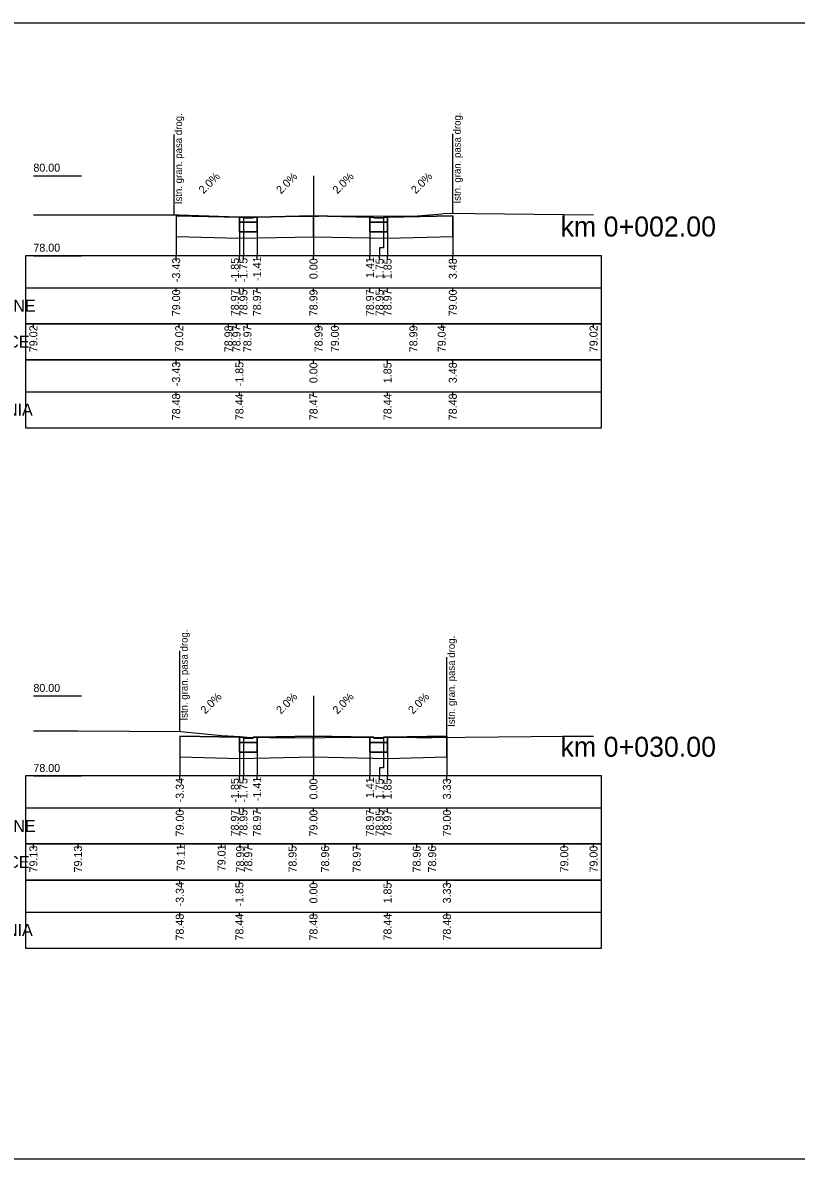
# Model space of a CAD drawing. Extents: x 7492871 to 7493499, y 5802964 to 5802992.
# Drawn here: x 7493176.28 to 7493195.61, y 5802963.88 to 5802992.28 of the extents above; entities that cross this region are included whole.
import ezdxf

# ---------------------------------------------------------------- set-up
doc = ezdxf.new("R2010")
doc.units = 0
for name, color, linetype in [('_wydruk', 7, 'Continuous'), ('opisy_ramki_pop', 7, 'Continuous'), ('pop_comp_kostka', 7, 'Continuous'), ('pop_comp_lawa', 7, 'Continuous'), ('pop_comp_scieralna', 7, 'Continuous'), ('pop_granica_istn', 7, 'Continuous'), ('pop_opis', 7, 'Continuous'), ('pop_os', 7, 'Continuous'), ('pop_pikietaz', 7, 'Continuous'), ('pop_teren', 7, 'Continuous')]:
    doc.layers.add(name, color=color, linetype=linetype)

msp = doc.modelspace()

# ---------------------------------------------------------------- linework, layer by layer
for points in [[(7493180.111, 5802987.456), (7493181.692, 5802987.425), (7493181.792, 5802987.425), (7493181.793, 5802987.405), (7493182.032, 5802987.405), (7493182.033, 5802987.425), (7493182.133, 5802987.425), (7493183.543, 5802987.453), (7493184.953, 5802987.425), (7493185.053, 5802987.425), (7493185.054, 5802987.405), (7493185.293, 5802987.405), (7493185.294, 5802987.425), (7493185.394, 5802987.425), (7493187.025, 5802987.457)], [(7493180.201, 5802974.456), (7493181.692, 5802974.426), (7493181.792, 5802974.426), (7493181.793, 5802974.406), (7493182.032, 5802974.406), (7493182.033, 5802974.426), (7493182.133, 5802974.426), (7493183.543, 5802974.454), (7493184.953, 5802974.426), (7493185.053, 5802974.426), (7493185.054, 5802974.406), (7493185.293, 5802974.406), (7493185.294, 5802974.426), (7493185.394, 5802974.426), (7493186.877, 5802974.456)]]:
    msp.add_lwpolyline(points)
at = {"layer": '_wydruk'}
msp.add_lwpolyline([(7492871.369, 5802992.281), (7493499.283, 5802992.281), (7493499.283, 5802963.881), (7492871.369, 5802963.881)], close=True, dxfattribs=at)
at = {"layer": 'opisy_ramki_pop'}
for points in [[(7493180.111, 5802986.936), (7493180.111, 5802986.659), (7493180.111, 5802986.659), (7493180.111, 5802986.459)], [(7493181.692, 5802986.896), (7493181.692, 5802986.659), (7493181.692, 5802986.659), (7493181.692, 5802986.459)], [(7493183.543, 5802986.933), (7493183.543, 5802986.659), (7493183.543, 5802986.659), (7493183.543, 5802986.459)], [(7493185.394, 5802986.896), (7493185.394, 5802986.659), (7493185.394, 5802986.659), (7493185.394, 5802986.459)], [(7493187.025, 5802986.937), (7493187.025, 5802986.659), (7493187.025, 5802986.659), (7493187.025, 5802986.459)], [(7493180.201, 5802973.936), (7493180.201, 5802973.659), (7493180.201, 5802973.659), (7493180.201, 5802973.459)], [(7493181.692, 5802973.897), (7493181.692, 5802973.659), (7493181.692, 5802973.659), (7493181.692, 5802973.459)], [(7493183.543, 5802973.934), (7493183.543, 5802973.659), (7493183.543, 5802973.659), (7493183.543, 5802973.459)], [(7493185.394, 5802973.897), (7493185.394, 5802973.659), (7493185.394, 5802973.659), (7493185.394, 5802973.459)], [(7493186.877, 5802973.936), (7493186.877, 5802973.659), (7493186.877, 5802973.659), (7493186.877, 5802973.459)]]:
    msp.add_lwpolyline(points, dxfattribs=at)
at = {"layer": 'pop_comp_kostka'}
for p, q in [((7493181.792, 5802987.425), (7493181.692, 5802987.425)), ((7493181.692, 5802987.425), (7493181.692, 5802987.295)), ((7493181.793, 5802987.405), (7493181.792, 5802987.425)), ((7493182.032, 5802987.405), (7493181.793, 5802987.405)), ((7493182.033, 5802987.425), (7493182.032, 5802987.405)), ((7493182.133, 5802987.425), (7493182.033, 5802987.425)), ((7493182.133, 5802987.295), (7493182.133, 5802987.425)), ((7493185.053, 5802987.425), (7493184.953, 5802987.425)), ((7493184.953, 5802987.425), (7493184.953, 5802987.295)), ((7493185.054, 5802987.405), (7493185.053, 5802987.425)), ((7493185.293, 5802987.405), (7493185.054, 5802987.405)), ((7493185.294, 5802987.425), (7493185.293, 5802987.405)), ((7493185.394, 5802987.425), (7493185.294, 5802987.425)), ((7493185.394, 5802987.295), (7493185.394, 5802987.425)), ((7493181.692, 5802987.295), (7493182.133, 5802987.295)), ((7493184.953, 5802987.295), (7493185.394, 5802987.295)), ((7493181.792, 5802974.426), (7493181.692, 5802974.426)), ((7493181.692, 5802974.426), (7493181.692, 5802974.296)), ((7493181.692, 5802974.296), (7493182.133, 5802974.296)), ((7493181.793, 5802974.406), (7493181.792, 5802974.426)), ((7493182.032, 5802974.406), (7493181.793, 5802974.406)), ((7493182.033, 5802974.426), (7493182.032, 5802974.406)), ((7493182.133, 5802974.426), (7493182.033, 5802974.426)), ((7493182.133, 5802974.296), (7493182.133, 5802974.426)), ((7493185.053, 5802974.426), (7493184.953, 5802974.426)), ((7493184.953, 5802974.426), (7493184.953, 5802974.296)), ((7493184.953, 5802974.296), (7493185.394, 5802974.296)), ((7493185.054, 5802974.406), (7493185.053, 5802974.426)), ((7493185.293, 5802974.406), (7493185.054, 5802974.406)), ((7493185.294, 5802974.426), (7493185.293, 5802974.406)), ((7493185.394, 5802974.426), (7493185.294, 5802974.426)), ((7493185.394, 5802974.296), (7493185.394, 5802974.426))]:
    msp.add_line(p, q, dxfattribs=at)
at = {"layer": 'pop_comp_lawa'}
for p, q in [((7493182.133, 5802987.295), (7493181.692, 5802987.295)), ((7493181.692, 5802987.295), (7493181.692, 5802987.055)), ((7493181.692, 5802987.055), (7493182.133, 5802987.055)), ((7493182.133, 5802987.055), (7493182.133, 5802987.295)), ((7493185.394, 5802987.295), (7493184.953, 5802987.295)), ((7493184.953, 5802987.295), (7493184.953, 5802987.055)), ((7493184.953, 5802987.055), (7493185.394, 5802987.055)), ((7493185.394, 5802987.055), (7493185.394, 5802987.295)), ((7493182.133, 5802974.296), (7493181.692, 5802974.296)), ((7493181.692, 5802974.296), (7493181.692, 5802974.056)), ((7493182.133, 5802974.056), (7493182.133, 5802974.296)), ((7493185.394, 5802974.296), (7493184.953, 5802974.296)), ((7493184.953, 5802974.296), (7493184.953, 5802974.056)), ((7493185.394, 5802974.056), (7493185.394, 5802974.296)), ((7493181.692, 5802974.056), (7493182.133, 5802974.056)), ((7493184.953, 5802974.056), (7493185.394, 5802974.056))]:
    msp.add_line(p, q, dxfattribs=at)
at = {"layer": 'pop_comp_scieralna'}
for p, q in [((7493181.692, 5802987.425), (7493180.111, 5802987.456)), ((7493180.111, 5802987.456), (7493180.111, 5802986.936)), ((7493181.692, 5802987.055), (7493181.692, 5802987.425)), ((7493183.543, 5802987.453), (7493182.133, 5802987.425)), ((7493182.133, 5802987.425), (7493182.133, 5802987.055)), ((7493183.543, 5802986.933), (7493183.543, 5802987.453)), ((7493184.953, 5802987.425), (7493183.543, 5802987.453)), ((7493183.543, 5802987.453), (7493183.543, 5802986.933)), ((7493184.953, 5802987.055), (7493184.953, 5802987.425)), ((7493187.025, 5802987.457), (7493185.394, 5802987.425)), ((7493185.394, 5802987.425), (7493185.394, 5802987.055)), ((7493187.025, 5802986.937), (7493187.025, 5802987.457)), ((7493182.133, 5802987.055), (7493181.692, 5802987.055)), ((7493185.394, 5802987.055), (7493184.953, 5802987.055)), ((7493180.111, 5802986.936), (7493181.692, 5802986.896)), ((7493181.692, 5802986.896), (7493183.543, 5802986.933)), ((7493183.543, 5802986.933), (7493185.394, 5802986.896)), ((7493185.394, 5802986.896), (7493187.025, 5802986.937)), ((7493181.692, 5802974.426), (7493180.201, 5802974.456)), ((7493180.201, 5802974.456), (7493180.201, 5802973.936)), ((7493181.692, 5802974.056), (7493181.692, 5802974.426)), ((7493183.543, 5802974.454), (7493182.133, 5802974.426)), ((7493182.133, 5802974.426), (7493182.133, 5802974.056)), ((7493183.543, 5802973.934), (7493183.543, 5802974.454)), ((7493184.953, 5802974.426), (7493183.543, 5802974.454)), ((7493183.543, 5802974.454), (7493183.543, 5802973.934)), ((7493184.953, 5802974.056), (7493184.953, 5802974.426)), ((7493186.877, 5802974.456), (7493185.394, 5802974.426)), ((7493185.394, 5802974.426), (7493185.394, 5802974.056)), ((7493186.877, 5802973.936), (7493186.877, 5802974.456)), ((7493182.133, 5802974.056), (7493181.692, 5802974.056)), ((7493185.394, 5802974.056), (7493184.953, 5802974.056)), ((7493180.201, 5802973.936), (7493181.692, 5802973.897)), ((7493181.692, 5802973.897), (7493183.543, 5802973.934)), ((7493183.543, 5802973.934), (7493185.394, 5802973.897)), ((7493185.394, 5802973.897), (7493186.877, 5802973.936))]:
    msp.add_line(p, q, dxfattribs=at)
at = {"layer": 'pop_granica_istn'}
for p, q in [((7493180.06, 5802987.984), (7493180.06, 5802989.484)), ((7493187.025, 5802988.002), (7493187.025, 5802989.502)), ((7493180.06, 5802987.484), (7493180.06, 5802987.984)), ((7493187.025, 5802987.502), (7493187.025, 5802988.002)), ((7493180.201, 5802975.082), (7493180.201, 5802976.582)), ((7493186.88, 5802974.924), (7493186.88, 5802976.424)), ((7493180.201, 5802974.582), (7493180.201, 5802975.082)), ((7493186.88, 5802974.424), (7493186.88, 5802974.924))]:
    msp.add_line(p, q, dxfattribs=at)
at = {"layer": 'pop_opis'}
for p, q in [((7493176.543, 5802988.459), (7493177.743, 5802988.459)), ((7493176.343, 5802986.459), (7493176.343, 5802984.759)), ((7493176.343, 5802986.459), (7493176.343, 5802984.759)), ((7493176.343, 5802986.459), (7493176.343, 5802984.759)), ((7493176.343, 5802986.459), (7493176.343, 5802984.759)), ((7493176.543, 5802986.459), (7493177.743, 5802986.459)), ((7493180.111, 5802986.359), (7493180.111, 5802986.459)), ((7493181.692, 5802986.359), (7493181.692, 5802986.459)), ((7493181.793, 5802986.359), (7493181.793, 5802986.459)), ((7493182.133, 5802986.359), (7493182.133, 5802986.459)), ((7493183.543, 5802986.359), (7493183.543, 5802986.459)), ((7493184.953, 5802986.359), (7493184.953, 5802986.459)), ((7493185.194, 5802986.359), (7493185.194, 5802986.459)), ((7493185.394, 5802986.359), (7493185.394, 5802986.459)), ((7493187.025, 5802986.359), (7493187.025, 5802986.459)), ((7493176.343, 5802985.659), (7493190.743, 5802985.659)), ((7493176.343, 5802985.659), (7493190.743, 5802985.659)), ((7493176.343, 5802985.659), (7493190.743, 5802985.659)), ((7493176.343, 5802985.659), (7493190.743, 5802985.659)), ((7493180.111, 5802985.559), (7493180.111, 5802985.659)), ((7493181.692, 5802985.559), (7493181.692, 5802985.659)), ((7493181.793, 5802985.559), (7493181.793, 5802985.659)), ((7493182.133, 5802985.559), (7493182.133, 5802985.659)), ((7493183.543, 5802985.559), (7493183.543, 5802985.659)), ((7493184.953, 5802985.559), (7493184.953, 5802985.659)), ((7493185.194, 5802985.559), (7493185.194, 5802985.659)), ((7493185.394, 5802985.559), (7493185.394, 5802985.659)), ((7493187.025, 5802985.559), (7493187.025, 5802985.659)), ((7493176.343, 5802984.759), (7493176.343, 5802983.859)), ((7493176.543, 5802984.659), (7493176.543, 5802984.759)), ((7493180.187, 5802984.659), (7493180.187, 5802984.759)), ((7493181.419, 5802984.659), (7493181.419, 5802984.759)), ((7493181.619, 5802984.659), (7493181.619, 5802984.759)), ((7493181.893, 5802984.659), (7493181.893, 5802984.759)), ((7493183.67, 5802984.659), (7493183.67, 5802984.759)), ((7493184.078, 5802984.659), (7493184.078, 5802984.759)), ((7493186.041, 5802984.659), (7493186.041, 5802984.759)), ((7493186.748, 5802984.659), (7493186.748, 5802984.759)), ((7493190.543, 5802984.659), (7493190.543, 5802984.759)), ((7493176.343, 5802983.859), (7493176.343, 5802982.159)), ((7493180.111, 5802983.759), (7493180.111, 5802983.859)), ((7493181.692, 5802983.759), (7493181.692, 5802983.859)), ((7493183.543, 5802983.759), (7493183.543, 5802983.859)), ((7493185.394, 5802983.759), (7493185.394, 5802983.859)), ((7493187.025, 5802983.759), (7493187.025, 5802983.859)), ((7493176.343, 5802983.059), (7493190.743, 5802983.059)), ((7493180.111, 5802982.959), (7493180.111, 5802983.059)), ((7493181.692, 5802982.959), (7493181.692, 5802983.059)), ((7493183.543, 5802982.959), (7493183.543, 5802983.059)), ((7493185.394, 5802982.959), (7493185.394, 5802983.059)), ((7493187.025, 5802982.959), (7493187.025, 5802983.059)), ((7493176.543, 5802975.459), (7493177.743, 5802975.459)), ((7493176.343, 5802973.459), (7493176.343, 5802971.759)), ((7493176.343, 5802973.459), (7493176.343, 5802971.759)), ((7493176.343, 5802973.459), (7493176.343, 5802971.759)), ((7493176.343, 5802973.459), (7493176.343, 5802971.759)), ((7493176.543, 5802973.459), (7493177.743, 5802973.459)), ((7493180.201, 5802973.359), (7493180.201, 5802973.459)), ((7493181.692, 5802973.359), (7493181.692, 5802973.459)), ((7493181.793, 5802973.359), (7493181.793, 5802973.459)), ((7493182.133, 5802973.359), (7493182.133, 5802973.459)), ((7493183.543, 5802973.359), (7493183.543, 5802973.459)), ((7493184.953, 5802973.359), (7493184.953, 5802973.459)), ((7493185.194, 5802973.359), (7493185.194, 5802973.459)), ((7493185.394, 5802973.359), (7493185.394, 5802973.459)), ((7493186.877, 5802973.359), (7493186.877, 5802973.459)), ((7493176.343, 5802972.659), (7493190.743, 5802972.659)), ((7493176.343, 5802972.659), (7493190.743, 5802972.659)), ((7493176.343, 5802972.659), (7493190.743, 5802972.659)), ((7493176.343, 5802972.659), (7493190.743, 5802972.659)), ((7493180.201, 5802972.559), (7493180.201, 5802972.659)), ((7493181.692, 5802972.559), (7493181.692, 5802972.659)), ((7493181.793, 5802972.559), (7493181.793, 5802972.659)), ((7493182.133, 5802972.559), (7493182.133, 5802972.659)), ((7493183.543, 5802972.559), (7493183.543, 5802972.659)), ((7493184.953, 5802972.559), (7493184.953, 5802972.659)), ((7493185.194, 5802972.559), (7493185.194, 5802972.659)), ((7493185.394, 5802972.559), (7493185.394, 5802972.659)), ((7493186.877, 5802972.559), (7493186.877, 5802972.659)), ((7493176.343, 5802971.759), (7493176.343, 5802970.859)), ((7493176.543, 5802971.659), (7493176.543, 5802971.759)), ((7493177.658, 5802971.659), (7493177.658, 5802971.759)), ((7493180.227, 5802971.659), (7493180.227, 5802971.759)), ((7493181.245, 5802971.659), (7493181.245, 5802971.759)), ((7493181.712, 5802971.659), (7493181.712, 5802971.759)), ((7493181.912, 5802971.659), (7493181.912, 5802971.759)), ((7493183.02, 5802971.659), (7493183.02, 5802971.759)), ((7493183.835, 5802971.659), (7493183.835, 5802971.759)), ((7493184.624, 5802971.659), (7493184.624, 5802971.759)), ((7493186.123, 5802971.659), (7493186.123, 5802971.759)), ((7493186.509, 5802971.659), (7493186.509, 5802971.759)), ((7493189.812, 5802971.659), (7493189.812, 5802971.759)), ((7493190.543, 5802971.659), (7493190.543, 5802971.759)), ((7493176.343, 5802970.859), (7493176.343, 5802969.159)), ((7493180.201, 5802970.759), (7493180.201, 5802970.859)), ((7493181.692, 5802970.759), (7493181.692, 5802970.859)), ((7493183.543, 5802970.759), (7493183.543, 5802970.859)), ((7493185.394, 5802970.759), (7493185.394, 5802970.859)), ((7493186.877, 5802970.759), (7493186.877, 5802970.859)), ((7493176.343, 5802970.059), (7493190.743, 5802970.059)), ((7493180.201, 5802969.959), (7493180.201, 5802970.059)), ((7493181.692, 5802969.959), (7493181.692, 5802970.059)), ((7493183.543, 5802969.959), (7493183.543, 5802970.059)), ((7493185.394, 5802969.959), (7493185.394, 5802970.059)), ((7493186.877, 5802969.959), (7493186.877, 5802970.059))]:
    msp.add_line(p, q, dxfattribs=at)
for points in [[(7493180.111, 5802987.456), (7493180.111, 5802986.659), (7493180.111, 5802986.659), (7493180.111, 5802986.459)], [(7493181.692, 5802987.425), (7493181.692, 5802986.659), (7493181.692, 5802986.659), (7493181.692, 5802986.459)], [(7493181.793, 5802987.405), (7493181.793, 5802986.659), (7493181.793, 5802986.659), (7493181.793, 5802986.459)], [(7493182.133, 5802987.425), (7493182.133, 5802986.659), (7493182.133, 5802986.659), (7493182.133, 5802986.459)], [(7493183.543, 5802987.453), (7493183.543, 5802986.659), (7493183.543, 5802986.659), (7493183.543, 5802986.459)], [(7493184.953, 5802987.425), (7493184.953, 5802986.659), (7493184.953, 5802986.659), (7493184.953, 5802986.459)], [(7493185.293, 5802987.405), (7493185.293, 5802986.659), (7493185.194, 5802986.659), (7493185.194, 5802986.459)], [(7493185.394, 5802987.425), (7493185.394, 5802986.659), (7493185.394, 5802986.659), (7493185.394, 5802986.459)], [(7493187.025, 5802987.457), (7493187.025, 5802986.659), (7493187.025, 5802986.659), (7493187.025, 5802986.459)], [(7493180.201, 5802974.456), (7493180.201, 5802973.659), (7493180.201, 5802973.659), (7493180.201, 5802973.459)], [(7493181.692, 5802974.426), (7493181.692, 5802973.659), (7493181.692, 5802973.659), (7493181.692, 5802973.459)], [(7493181.793, 5802974.406), (7493181.793, 5802973.659), (7493181.793, 5802973.659), (7493181.793, 5802973.459)], [(7493182.133, 5802974.426), (7493182.133, 5802973.659), (7493182.133, 5802973.659), (7493182.133, 5802973.459)], [(7493183.543, 5802974.454), (7493183.543, 5802973.659), (7493183.543, 5802973.659), (7493183.543, 5802973.459)], [(7493184.953, 5802974.426), (7493184.953, 5802973.659), (7493184.953, 5802973.659), (7493184.953, 5802973.459)], [(7493185.293, 5802974.406), (7493185.293, 5802973.659), (7493185.194, 5802973.659), (7493185.194, 5802973.459)], [(7493185.394, 5802974.426), (7493185.394, 5802973.659), (7493185.394, 5802973.659), (7493185.394, 5802973.459)], [(7493186.877, 5802974.456), (7493186.877, 5802973.659), (7493186.877, 5802973.659), (7493186.877, 5802973.459)]]:
    msp.add_lwpolyline(points, dxfattribs=at)
for points in [[(7493176.343, 5802986.459), (7493176.343, 5802984.759), (7493190.743, 5802984.759), (7493190.743, 5802986.459)], [(7493176.343, 5802986.459), (7493176.343, 5802984.759), (7493190.743, 5802984.759), (7493190.743, 5802986.459)], [(7493176.343, 5802986.459), (7493176.343, 5802984.759), (7493190.743, 5802984.759), (7493190.743, 5802986.459)], [(7493176.343, 5802986.459), (7493176.343, 5802984.759), (7493190.743, 5802984.759), (7493190.743, 5802986.459)], [(7493176.343, 5802984.759), (7493176.343, 5802983.859), (7493190.743, 5802983.859), (7493190.743, 5802984.759)], [(7493176.343, 5802983.859), (7493176.343, 5802982.159), (7493190.743, 5802982.159), (7493190.743, 5802983.859)], [(7493176.343, 5802973.459), (7493176.343, 5802971.759), (7493190.743, 5802971.759), (7493190.743, 5802973.459)], [(7493176.343, 5802973.459), (7493176.343, 5802971.759), (7493190.743, 5802971.759), (7493190.743, 5802973.459)], [(7493176.343, 5802973.459), (7493176.343, 5802971.759), (7493190.743, 5802971.759), (7493190.743, 5802973.459)], [(7493176.343, 5802973.459), (7493176.343, 5802971.759), (7493190.743, 5802971.759), (7493190.743, 5802973.459)], [(7493176.343, 5802971.759), (7493176.343, 5802970.859), (7493190.743, 5802970.859), (7493190.743, 5802971.759)], [(7493176.343, 5802970.859), (7493176.343, 5802969.159), (7493190.743, 5802969.159), (7493190.743, 5802970.859)]]:
    msp.add_lwpolyline(points, close=True, dxfattribs=at)
at = {"layer": 'pop_os'}
for p, q in [((7493183.543, 5802988.459), (7493183.543, 5802986.459)), ((7493183.543, 5802975.459), (7493183.543, 5802973.459))]:
    msp.add_line(p, q, dxfattribs=at)
at = {"layer": 'pop_teren'}
for points in [[(7493176.543, 5802987.482), (7493180.187, 5802987.478), (7493181.419, 5802987.441), (7493181.593, 5802987.431), (7493181.893, 5802987.431), (7493183.67, 5802987.45), (7493184.078, 5802987.455), (7493186.041, 5802987.444), (7493186.748, 5802987.502), (7493186.84, 5802987.523), (7493190.543, 5802987.482)], [(7493176.543, 5802974.584), (7493177.658, 5802974.585), (7493180.227, 5802974.569), (7493181.245, 5802974.471), (7493181.712, 5802974.446), (7493181.884, 5802974.431), (7493183.02, 5802974.413), (7493183.835, 5802974.42), (7493184.624, 5802974.429), (7493186.123, 5802974.42), (7493186.509, 5802974.418), (7493189.812, 5802974.456), (7493190.543, 5802974.455)]]:
    msp.add_lwpolyline(points, dxfattribs=at)

# ---------------------------------------------------------------- texts
at = {"layer": 'pop_granica_istn'}
for p in [(7493180.258, 5802987.745), (7493187.223, 5802987.763), (7493180.399, 5802974.843), (7493187.078, 5802974.686)]:
    msp.add_text('Istn. gran. pasa drog.', height=0.18, rotation=90, dxfattribs=at).set_placement(p)
at = {"layer": 'pop_opis'}
for s, height, p in [('80.00', 0.2, (7493176.543, 5802988.559)), ('78.00', 0.2, (7493176.543, 5802986.559)), ('RZĘDNE PROJEKTOWANE', 0.3, (7493171.471, 5802985.059)), ('RZĘDNE PROJEKTOWANE', 0.3, (7493171.471, 5802985.059)), ('RZĘDNE PROJEKTOWANE', 0.3, (7493171.471, 5802985.059)), ('RZĘDNE PROJEKTOWANE', 0.3, (7493171.471, 5802985.059)), ('RZĘDNE ISTNIEJĄCE', 0.3, (7493172.367, 5802984.159)), ('RZĘDNE KORYTOWANIA', 0.3, (7493171.757, 5802982.459)), ('80.00', 0.2, (7493176.543, 5802975.559)), ('78.00', 0.2, (7493176.543, 5802973.559)), ('RZĘDNE PROJEKTOWANE', 0.3, (7493171.471, 5802972.059)), ('RZĘDNE PROJEKTOWANE', 0.3, (7493171.471, 5802972.059)), ('RZĘDNE PROJEKTOWANE', 0.3, (7493171.471, 5802972.059)), ('RZĘDNE PROJEKTOWANE', 0.3, (7493171.471, 5802972.059)), ('RZĘDNE ISTNIEJĄCE', 0.3, (7493172.367, 5802971.159)), ('RZĘDNE KORYTOWANIA', 0.3, (7493171.757, 5802969.459))]:
    msp.add_text(s, height=height, dxfattribs=at).set_placement(p)
for s, rotation, p in [('2.0%', 45, (7493180.793, 5802987.99)), ('2.0%', 45, (7493182.729, 5802987.989)), ('2.0%', 45, (7493184.139, 5802987.989)), ('2.0%', 45, (7493186.101, 5802987.991)), ('-3.43', 90, (7493180.211, 5802985.798)), ('-1.85', 90, (7493181.678, 5802985.796)), ('-1.75', 90, (7493181.893, 5802985.796)), ('-1.41', 90, (7493182.233, 5802985.829)), ('0.00', 90, (7493183.643, 5802985.874)), ('1.41', 90, (7493185.053, 5802985.905)), ('1.75', 90, (7493185.294, 5802985.873)), ('1.85', 90, (7493185.494, 5802985.873)), ('3.48', 90, (7493187.125, 5802985.873)), ('79.00', 90, (7493180.211, 5802984.947)), ('78.97', 90, (7493181.678, 5802984.947)), ('78.95', 90, (7493181.893, 5802984.945)), ('78.97', 90, (7493182.233, 5802984.947)), ('78.99', 90, (7493183.643, 5802984.946)), ('78.97', 90, (7493185.053, 5802984.947)), ('78.95', 90, (7493185.294, 5802984.945)), ('78.97', 90, (7493185.494, 5802984.947)), ('79.00', 90, (7493187.125, 5802984.947)), ('79.02', 90, (7493176.643, 5802984.048)), ('79.02', 90, (7493180.287, 5802984.048)), ('78.98', 90, (7493181.519, 5802984.046)), ('78.97', 90, (7493181.719, 5802984.047)), ('78.97', 90, (7493181.993, 5802984.047)), ('78.99', 90, (7493183.77, 5802984.046)), ('79.00', 90, (7493184.178, 5802984.047)), ('78.99', 90, (7493186.141, 5802984.046)), ('79.04', 90, (7493186.848, 5802984.047)), ('79.02', 90, (7493190.643, 5802984.048)), ('-3.43', 90, (7493180.211, 5802983.198)), ('-1.85', 90, (7493181.792, 5802983.196)), ('0.00', 90, (7493183.643, 5802983.274)), ('1.85', 90, (7493185.494, 5802983.273)), ('3.48', 90, (7493187.125, 5802983.273)), ('78.48', 90, (7493180.211, 5802982.346)), ('78.44', 90, (7493181.792, 5802982.347)), ('78.47', 90, (7493183.643, 5802982.347)), ('78.44', 90, (7493185.494, 5802982.347)), ('78.48', 90, (7493187.125, 5802982.346)), ('2.0%', 45, (7493180.838, 5802974.991)), ('2.0%', 45, (7493182.729, 5802974.99)), ('2.0%', 45, (7493184.139, 5802974.99)), ('2.0%', 45, (7493186.027, 5802974.991)), ('-1.41', 90, (7493182.233, 5802972.829)), ('-3.34', 90, (7493180.301, 5802972.798)), ('-1.85', 90, (7493181.678, 5802972.796)), ('-1.75', 90, (7493181.893, 5802972.796)), ('0.00', 90, (7493183.643, 5802972.874)), ('1.41', 90, (7493185.053, 5802972.905)), ('1.75', 90, (7493185.294, 5802972.873)), ('1.85', 90, (7493185.494, 5802972.873)), ('3.33', 90, (7493186.977, 5802972.874)), ('79.00', 90, (7493180.301, 5802971.947)), ('78.97', 90, (7493181.678, 5802971.947)), ('78.95', 90, (7493181.893, 5802971.945)), ('78.97', 90, (7493182.233, 5802971.947)), ('79.00', 90, (7493183.643, 5802971.947)), ('78.97', 90, (7493185.053, 5802971.947)), ('78.95', 90, (7493185.294, 5802971.945)), ('78.97', 90, (7493185.494, 5802971.947)), ('79.00', 90, (7493186.977, 5802971.947)), ('79.11', 90, (7493180.327, 5802971.078)), ('79.01', 90, (7493181.345, 5802971.078)), ('79.13', 90, (7493176.643, 5802971.047)), ('79.13', 90, (7493177.758, 5802971.047)), ('78.99', 90, (7493181.812, 5802971.046)), ('78.97', 90, (7493182.012, 5802971.047)), ('78.95', 90, (7493183.12, 5802971.045)), ('78.96', 90, (7493183.935, 5802971.047)), ('78.97', 90, (7493184.724, 5802971.047)), ('78.96', 90, (7493186.223, 5802971.047)), ('78.96', 90, (7493186.609, 5802971.047)), ('79.00', 90, (7493189.912, 5802971.047)), ('79.00', 90, (7493190.643, 5802971.047)), ('-3.34', 90, (7493180.301, 5802970.198)), ('-1.85', 90, (7493181.792, 5802970.196)), ('0.00', 90, (7493183.643, 5802970.274)), ('1.85', 90, (7493185.494, 5802970.273)), ('3.33', 90, (7493186.977, 5802970.274)), ('78.48', 90, (7493180.301, 5802969.346)), ('78.44', 90, (7493181.792, 5802969.347)), ('78.48', 90, (7493183.643, 5802969.346)), ('78.44', 90, (7493185.494, 5802969.347)), ('78.48', 90, (7493186.977, 5802969.346))]:
    msp.add_text(s, height=0.2, rotation=rotation, dxfattribs=at).set_placement(p)
at = {"layer": 'pop_pikietaz'}
for s, p in [('km 0+002.00', (7493189.719, 5802986.939)), ('km 0+030.00', (7493189.719, 5802973.939))]:
    msp.add_text(s, height=0.5, dxfattribs=at).set_placement(p)

doc.saveas('drawing.dxf')
